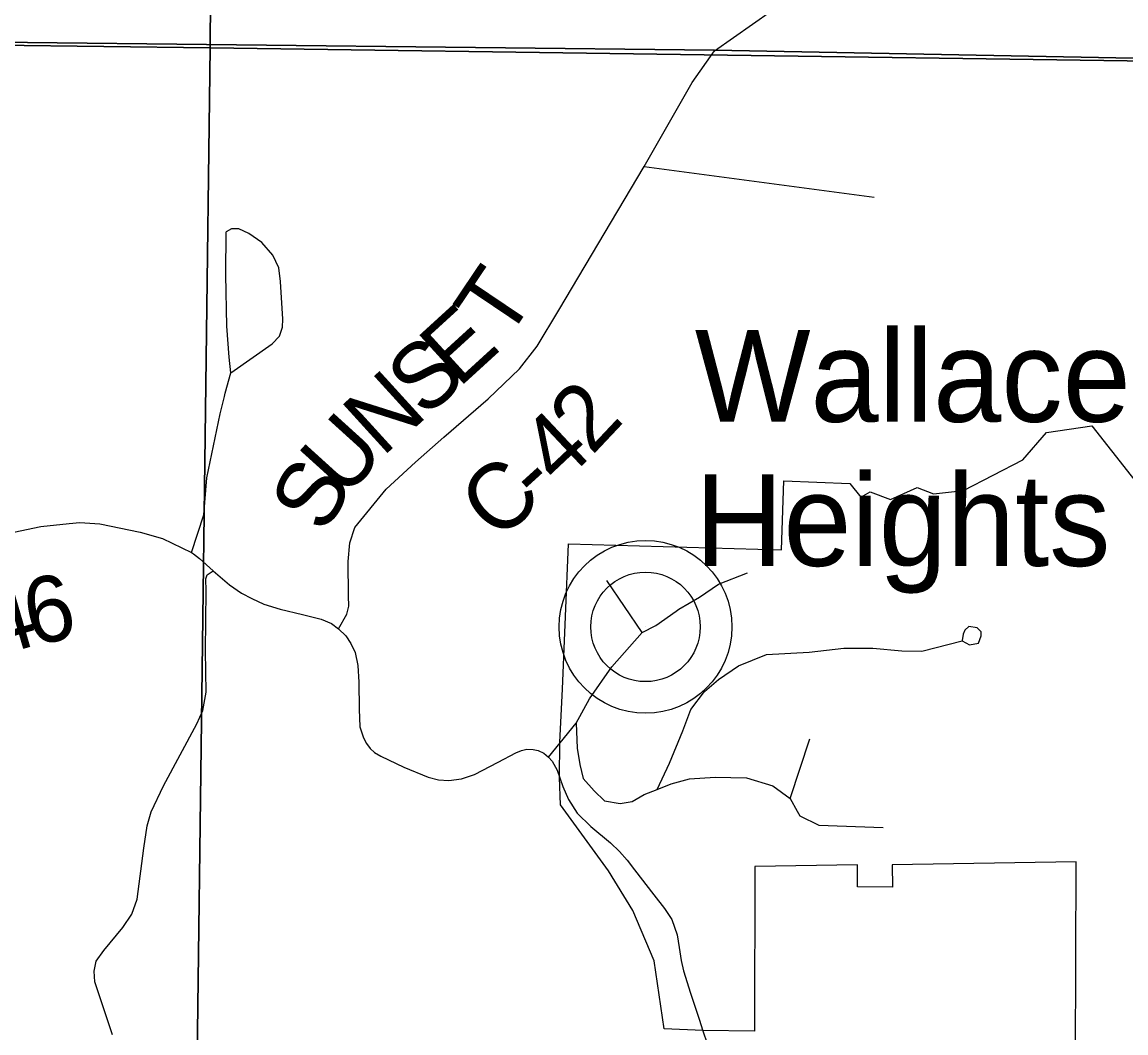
# Model space of a CAD drawing. Extents: x 2.1 to 8.9, y 14.1 to 20.9.
# Drawn here: x 6.298 to 7.249, y 18.274 to 19.144 of the extents above; entities that cross this region are included whole.
import ezdxf

# ---------------------------------------------------------------- set-up
doc = ezdxf.new("R2010")
doc.units = 0
for name, color, linetype in [('Default', 7, 'Continuous'), ('GM_X_City_Street', 7, 'Continuous'), ('GM_X_Interchange_Ramps', 7, 'Continuous'), ('GM_X_Major_River', 7, 'Continuous'), ('GM_X_Minor_River', 7, 'Continuous'), ('GM_X_State_Route', 7, 'Continuous'), ('GM_X_State_Shield', 7, 'Continuous'), ('GM_X_Township_Road', 7, 'Continuous'), ('GM_X_Township_Text', 7, 'Continuous')]:
    doc.layers.add(name, color=color, linetype=linetype)

msp = doc.modelspace()

# ---------------------------------------------------------------- linework, layer by layer
at = {"layer": 'Default'}
for p, q in [((6.89441, 19.12038), (5.40049, 19.13693)), ((5.40049, 19.13693), (6.89441, 19.12038)), ((7.43931, 19.10971), (6.89441, 19.12038)), ((6.89441, 19.12038), (7.43931, 19.10971))]:
    msp.add_line(p, q, dxfattribs=at)
at = {"layer": 'GM_X_City_Street'}
for p, q in [((6.83381, 19.02018), (7.03213, 18.99371)), ((6.47837, 18.96641), (6.47368, 18.96385)), ((6.48449, 18.96624), (6.47837, 18.96641)), ((6.49333, 18.96239), (6.48449, 18.96624)), ((6.47337, 18.92673), (6.47368, 18.96385)), ((6.50445, 18.95449), (6.49333, 18.96239)), ((6.51381, 18.94357), (6.50445, 18.95449)), ((6.51901, 18.93276), (6.51381, 18.94357)), ((6.52046, 18.92102), (6.51901, 18.93276)), ((6.47441, 18.88265), (6.47337, 18.92673)), ((6.52252, 18.88842), (6.52046, 18.92102)), ((6.47628, 18.85572), (6.47441, 18.88265)), ((6.5197, 18.87394), (6.52212, 18.88171)), ((6.52212, 18.88171), (6.52252, 18.88842)), ((6.51327, 18.86724), (6.5197, 18.87394)), ((6.47762, 18.84231), (6.51327, 18.86724)), ((6.47762, 18.84231), (6.47628, 18.85572)), ((6.47288, 18.82472), (6.47762, 18.84231)), ((6.47213, 18.82194), (6.47288, 18.82472)), ((6.46851, 18.80706), (6.47213, 18.82194)), ((6.4571, 18.75193), (6.46851, 18.80706)), ((6.45439, 18.72008), (6.4571, 18.75193)), ((6.44396, 18.68761), (6.45439, 18.72008)), ((6.45746, 18.66832), (6.46244, 18.67177)), ((6.4561, 18.66498), (6.45746, 18.66832)), ((6.45655, 18.65439), (6.4561, 18.66498)), ((6.83209, 18.61853), (6.80168, 18.66329)), ((6.89804, 18.66022), (6.92298, 18.67013)), ((6.4559, 18.60274), (6.45655, 18.65439)), ((6.88163, 18.64894), (6.89804, 18.66022)), ((6.86386, 18.63868), (6.88163, 18.64894)), ((6.84405, 18.62468), (6.86148, 18.637)), ((6.86148, 18.637), (6.86386, 18.63868)), ((6.83209, 18.61853), (6.84405, 18.62468)), ((7.11349, 18.62367), (7.11014, 18.62057)), ((7.12069, 18.62265), (7.11349, 18.62367)), ((6.80612, 18.58914), (6.83209, 18.61853)), ((7.10868, 18.61713), (7.10802, 18.6118)), ((7.11014, 18.62057), (7.10868, 18.61713)), ((7.12437, 18.61911), (7.12069, 18.62265)), ((7.12206, 18.6094), (7.12437, 18.61588)), ((7.12437, 18.61588), (7.12437, 18.61911)), ((6.97594, 18.60161), (7.00601, 18.60507)), ((7.00601, 18.60507), (7.03098, 18.60513)), ((7.03098, 18.60513), (7.05598, 18.60292)), ((7.07301, 18.60246), (7.10802, 18.61143)), ((7.10802, 18.61143), (7.11414, 18.60812)), ((7.11414, 18.60812), (7.12206, 18.6094)), ((6.4566, 18.56721), (6.4559, 18.60274)), ((6.91529, 18.58999), (6.93916, 18.59971)), ((6.93916, 18.59971), (6.97594, 18.60161)), ((7.05598, 18.60292), (7.07301, 18.60246)), ((6.78664, 18.56146), (6.80612, 18.58914)), ((6.89804, 18.57804), (6.91529, 18.58999)), ((6.88573, 18.56779), (6.89804, 18.57804)), ((6.45358, 18.55143), (6.4566, 18.56721)), ((6.87411, 18.55224), (6.88573, 18.56779)), ((6.77537, 18.54062), (6.78664, 18.56146)), ((6.44847, 18.53982), (6.45358, 18.55143)), ((6.86728, 18.53396), (6.87411, 18.55224)), ((6.41972, 18.48653), (6.44847, 18.53982)), ((6.76148, 18.52356), (6.77537, 18.54062)), ((6.77537, 18.54062), (6.77622, 18.5191)), ((6.85567, 18.50594), (6.86728, 18.53396)), ((6.75137, 18.51115), (6.76148, 18.52356)), ((6.77622, 18.5191), (6.77844, 18.50492)), ((6.95954, 18.47553), (6.97662, 18.52712)), ((6.77844, 18.50492), (6.78134, 18.49278)), ((6.84518, 18.4833), (6.85567, 18.50594)), ((6.78134, 18.49278), (6.79074, 18.48236)), ((6.85703, 18.48834), (6.87298, 18.49265)), ((6.87298, 18.49265), (6.89496, 18.49398)), ((6.89496, 18.49398), (6.92195, 18.4933)), ((6.92195, 18.4933), (6.94485, 18.48646)), ((6.4092, 18.46417), (6.41972, 18.48653)), ((6.79074, 18.48236), (6.79956, 18.47351)), ((6.83397, 18.47894), (6.84518, 18.4833)), ((6.84518, 18.4833), (6.85703, 18.48834)), ((6.94485, 18.48646), (6.95954, 18.47553)), ((6.79956, 18.47351), (6.81312, 18.47142)), ((6.81312, 18.47142), (6.82355, 18.47313)), ((6.82355, 18.47313), (6.83397, 18.47894)), ((6.95954, 18.47553), (6.96581, 18.46475)), ((6.40569, 18.45212), (6.4092, 18.46417)), ((6.96581, 18.46475), (6.96808, 18.46084)), ((6.40263, 18.43284), (6.40569, 18.45212)), ((6.96808, 18.46084), (6.98448, 18.45263)), ((6.98448, 18.45263), (7.03984, 18.45058)), ((6.39714, 18.38901), (6.40263, 18.43284)), ((6.39255, 18.37586), (6.39714, 18.38901)), ((6.38469, 18.36455), (6.39255, 18.37586)), ((6.36829, 18.34483), (6.38469, 18.36455)), ((6.36181, 18.33536), (6.36829, 18.34483)), ((6.35986, 18.32682), (6.36181, 18.33536)), ((6.36046, 18.31774), (6.35986, 18.32682)), ((6.3759, 18.27213), (6.36046, 18.31774))]:
    msp.add_line(p, q, dxfattribs=at)
at = {"layer": 'GM_X_Interchange_Ramps'}
for p, q in [((6.46652, 20.11672), (6.45993, 19.12233)), ((6.45993, 19.12233), (6.46652, 20.11672)), ((6.45993, 19.12233), (5.54579, 19.13355)), ((5.54579, 19.13355), (6.45993, 19.12233)), ((6.45993, 19.12233), (6.44653, 18.08952)), ((6.44653, 18.08952), (6.45993, 19.12233)), ((7.45846, 19.10807), (6.45993, 19.12233)), ((6.45993, 19.12233), (7.45846, 19.10807))]:
    msp.add_line(p, q, dxfattribs=at)
at = {"layer": 'GM_X_State_Route'}
for radius in [0.0744, 0.04716]:
    msp.add_circle((6.83506, 18.62346), radius, dxfattribs=at)
at = {"layer": 'GM_X_State_Shield'}
for p, q in [((6.89461, 19.11984), (7.00813, 19.19977)), ((6.87513, 19.09244), (6.89461, 19.11984)), ((6.84178, 19.03411), (6.87513, 19.09244)), ((6.83381, 19.02018), (6.84178, 19.03411)), ((6.76041, 18.89644), (6.83381, 19.02018)), ((6.74174, 18.86533), (6.76041, 18.89644)), ((6.72658, 18.84589), (6.74174, 18.86533)), ((6.69936, 18.81984), (6.72658, 18.84589)), ((6.66134, 18.78678), (6.69936, 18.81984)), ((6.63675, 18.76539), (6.66134, 18.78678)), ((6.61147, 18.74206), (6.63675, 18.76539)), ((6.58464, 18.709), (6.61147, 18.74206)), ((6.29071, 18.70506), (6.31396, 18.70994)), ((6.31396, 18.70994), (6.3383, 18.71266)), ((6.3383, 18.71266), (6.34771, 18.71329)), ((6.34771, 18.71329), (6.36472, 18.71239)), ((6.36472, 18.71239), (6.39946, 18.70497)), ((6.58036, 18.69578), (6.58464, 18.709)), ((6.39946, 18.70497), (6.41882, 18.69972)), ((6.41882, 18.69972), (6.44396, 18.68761)), ((6.5788, 18.67984), (6.58036, 18.69578)), ((6.44396, 18.68761), (6.44545, 18.68644)), ((6.44545, 18.68644), (6.45068, 18.68235)), ((6.45068, 18.68235), (6.46244, 18.67177)), ((6.46244, 18.67177), (6.47646, 18.65982)), ((6.57908, 18.65016), (6.5788, 18.67984)), ((6.47646, 18.65982), (6.48686, 18.65258)), ((6.48686, 18.65258), (6.49582, 18.64806)), ((6.49582, 18.64806), (6.50614, 18.64317)), ((6.50614, 18.64317), (6.52025, 18.63865)), ((6.57935, 18.6414), (6.57908, 18.65016)), ((6.52025, 18.63865), (6.53953, 18.6341)), ((6.53953, 18.6341), (6.55565, 18.63007)), ((6.5706, 18.62166), (6.57762, 18.63431)), ((6.57762, 18.63431), (6.57935, 18.6414)), ((6.55565, 18.63007), (6.56448, 18.62625)), ((6.56448, 18.62625), (6.5706, 18.62166)), ((6.5706, 18.62166), (6.57692, 18.61582)), ((6.57692, 18.61582), (6.58123, 18.60929)), ((6.58123, 18.60929), (6.58478, 18.6013)), ((6.58478, 18.6013), (6.58714, 18.59032)), ((6.58714, 18.59032), (6.58797, 18.57579)), ((6.58797, 18.57579), (6.58832, 18.55271)), ((6.58832, 18.55271), (6.58888, 18.53742)), ((6.58888, 18.53742), (6.592, 18.52776)), ((6.592, 18.52776), (6.59464, 18.5229)), ((6.59464, 18.5229), (6.59791, 18.51873)), ((6.59791, 18.51873), (6.60159, 18.51518)), ((6.60159, 18.51518), (6.60695, 18.51205)), ((6.60695, 18.51205), (6.62689, 18.50267)), ((6.70807, 18.50698), (6.72316, 18.51504)), ((6.72316, 18.51504), (6.72809, 18.51706)), ((6.72809, 18.51706), (6.73282, 18.51817)), ((6.73282, 18.51817), (6.7381, 18.51796)), ((6.7381, 18.51796), (6.74241, 18.51685)), ((6.74241, 18.51685), (6.74741, 18.5147)), ((6.74741, 18.5147), (6.75137, 18.51115)), ((6.75137, 18.51115), (6.75457, 18.50768)), ((6.62689, 18.50267), (6.64788, 18.49398)), ((6.68771, 18.49621), (6.70807, 18.50698)), ((6.75457, 18.50768), (6.75881, 18.5001)), ((6.75881, 18.5001), (6.76144, 18.49261)), ((6.64788, 18.49398), (6.65664, 18.49183)), ((6.65664, 18.49183), (6.66547, 18.4912)), ((6.66547, 18.4912), (6.67652, 18.49246)), ((6.67652, 18.49246), (6.68771, 18.49621)), ((6.76144, 18.49261), (6.76375, 18.48606)), ((6.76375, 18.48606), (6.76861, 18.47473)), ((6.76861, 18.47473), (6.77605, 18.46305)), ((6.77605, 18.46305), (6.78786, 18.45152)), ((6.78786, 18.45152), (6.80482, 18.43734)), ((6.80482, 18.43734), (6.81254, 18.43004)), ((6.81254, 18.43004), (6.81914, 18.42247)), ((6.81914, 18.42247), (6.82546, 18.41426)), ((6.82546, 18.41426), (6.84208, 18.39265)), ((6.84208, 18.39265), (6.85125, 18.38076)), ((6.85125, 18.38076), (6.85757, 18.37152)), ((6.85757, 18.37152), (6.86223, 18.35824)), ((6.86223, 18.35824), (6.86411, 18.34726)), ((6.86411, 18.34726), (6.86564, 18.33614)), ((6.86564, 18.33614), (6.86786, 18.32711)), ((6.86786, 18.32711), (6.87377, 18.30785)), ((6.87377, 18.30785), (6.88121, 18.28561)), ((6.88121, 18.28561), (6.88446, 18.27551)), ((6.88446, 18.27551), (6.88802, 18.26449))]:
    msp.add_line(p, q, dxfattribs=at)
at = {"layer": 'GM_X_Township_Road'}
for p, q in [((7.18043, 18.79107), (7.21974, 18.79679)), ((7.21974, 18.79679), (7.36788, 18.60674)), ((7.16002, 18.76729), (7.18043, 18.79107)), ((7.10912, 18.74086), (7.16002, 18.76729)), ((6.95221, 18.68996), (6.95427, 18.74935)), ((6.95427, 18.74935), (7.01099, 18.74709)), ((7.01099, 18.74709), (7.02044, 18.73523)), ((7.02044, 18.73523), (7.02873, 18.73977)), ((7.02873, 18.73977), (7.04614, 18.73311)), ((7.04614, 18.73311), (7.06897, 18.74367)), ((7.06897, 18.74367), (7.08321, 18.73809)), ((7.08321, 18.73809), (7.10912, 18.74086)), ((6.76356, 18.56974), (6.7687, 18.69509)), ((6.7687, 18.69509), (6.95221, 18.68996)), ((6.76127, 18.5241), (6.76356, 18.56974)), ((6.76106, 18.49369), (6.76127, 18.5241)), ((6.76191, 18.47027), (6.76106, 18.49369)), ((6.80302, 18.41335), (6.76191, 18.47027)), ((6.9292, 18.41704), (6.92899, 18.27525)), ((7.01756, 18.41848), (6.9292, 18.41704)), ((7.01777, 18.39958), (7.01756, 18.41848)), ((7.20609, 18.4212), (7.04757, 18.41848)), ((7.04757, 18.41848), (7.04798, 18.39937)), ((7.20512, 18.17173), (7.20609, 18.4212)), ((6.82398, 18.37903), (6.80302, 18.41335)), ((7.04798, 18.39937), (7.01777, 18.39958)), ((6.84247, 18.33587), (6.82398, 18.37903)), ((6.8511, 18.2773), (6.84247, 18.33587)), ((6.88434, 18.27584), (6.8511, 18.2773)), ((6.92899, 18.27525), (6.88434, 18.27584))]:
    msp.add_line(p, q, dxfattribs=at)
at = {"layer": 'GM_X_Township_Text'}
msp.add_line((6.83506, 18.62346), (6.83506, 18.62346), dxfattribs=at)

# ---------------------------------------------------------------- texts
at = {"layer": 'GM_X_Major_River'}
for s, p in [('Wallace', (6.87755, 18.80012)), ('Heights', (6.87755, 18.67596))]:
    msp.add_text(s, height=0.078977, rotation=0.00001, dxfattribs=at).set_placement(p)
at = {"layer": 'GM_X_Minor_River'}
for s, rotation, p in [('T', 56.0446, (6.71494, 18.86843)), ('E', 42.39486, (6.67392, 18.82861)), ('S', 41.88726, (6.64497, 18.80264)), ('N', 42.31755, (6.60808, 18.76906)), ('2', 46.69876, (6.78879, 18.7705)), ('U', 47.81133, (6.57552, 18.73303)), ('4', 43.24997, (6.76066, 18.74388)), ('C', 42.07888, (6.70784, 18.69603)), ('S', 61.2735, (6.55914, 18.70228)), ('-', 42.32856, (6.74267, 18.72749)), ('6', 12.12747, (6.30605, 18.60663)), ('4', 16.22455, (6.27349, 18.59712))]:
    msp.add_text(s, height=0.05682, rotation=rotation, dxfattribs=at).set_placement(p)

doc.saveas('drawing.dxf')
